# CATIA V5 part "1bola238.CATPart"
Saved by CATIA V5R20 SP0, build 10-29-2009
Part number: 1bola238
Revision: ANY
Definition: UNKNOWN
Nomenclature: 1bola238
Source: Unknown
Bounding box of the stored display mesh (mm): x -1.19 to 1.19, y -1.19 to 1.19, z -1.19 to 1.19
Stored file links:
  C:\Users\Utente\Desktop\IO LAVORO\3D X SITO CF\CUMSA\3D files BA\BA 061418\1bola238.CATPart
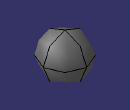
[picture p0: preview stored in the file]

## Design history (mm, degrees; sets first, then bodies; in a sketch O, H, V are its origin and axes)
Body1 "Revolución1" (main body)
  Solid1: solid without history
